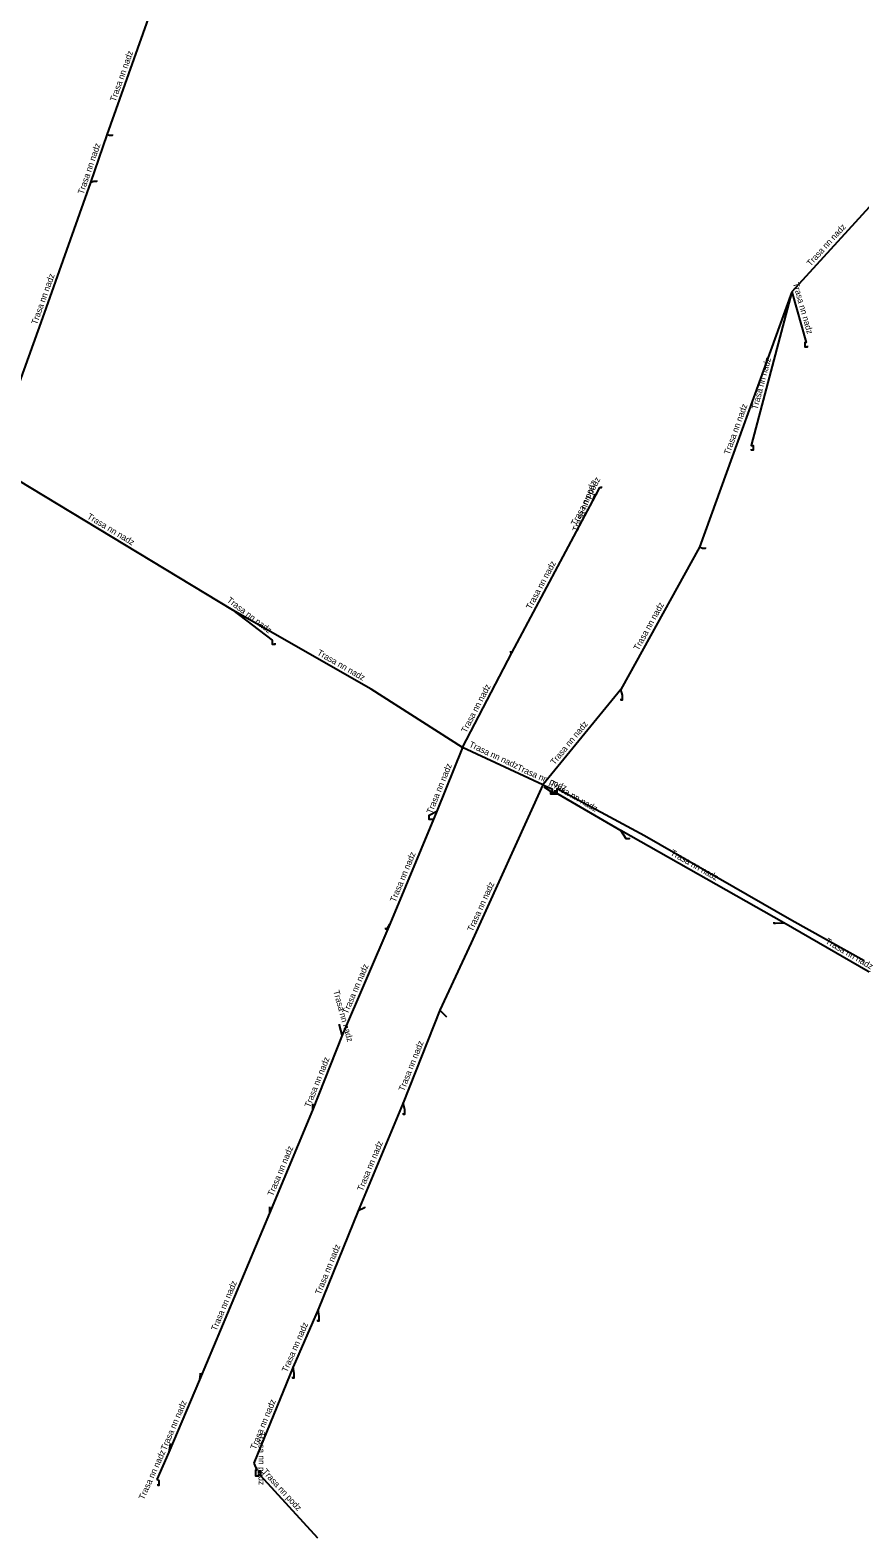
# Model space of a CAD drawing. Extents: x -742082 to -717476, y -1040737 to -1024597.
# Drawn here: x -736137.3 to -736004.4, y -1032673.2 to -1032431.7 of the extents above; entities that cross this region are included whole.
import ezdxf

# ---------------------------------------------------------------- set-up
doc = ezdxf.new("R2010")
doc.units = 0
for name, color, linetype in [('Level 13', 7, 'Continuous'), ('Level 14', 7, 'Continuous'), ('Level 15', 7, 'Continuous'), ('Level 20', 7, 'Continuous')]:
    doc.layers.add(name, color=color, linetype=linetype)

msp = doc.modelspace()

# ---------------------------------------------------------------- linework, layer by layer
at = {"layer": 'Level 13'}
for p, q in [((-736125, -1032448.5), (-736117.2, -1032426.5)), ((-736127.6, -1032456.1), (-736125, -1032448.5)), ((-736000.12, -1032456.95), (-736015.31, -1032473.63)), ((-736015.31, -1032473.63), (-736030.1, -1032514.5)), ((-736104.86, -1032524.63), (-736141.51, -1032502.48)), ((-736060.18, -1032531.44), (-736047.21, -1032507.11)), ((-736030.1, -1032514.5), (-736042.7, -1032537.3)), ((-736068.06, -1032546.59), (-736060.18, -1032531.44)), ((-736042.7, -1032537.3), (-736055.22, -1032552.57)), ((-736068.06, -1032546.59), (-736072.2, -1032556.8)), ((-736055.22, -1032552.57), (-736068.06, -1032546.59)), ((-736072.2, -1032556.8), (-736079.7, -1032574.9)), ((-736016.6, -1032574.7), (-736042.7, -1032559.9)), ((-736079.7, -1032574.9), (-736087.34, -1032592.71)), ((-735993.1, -1032588.3), (-736016.6, -1032574.7)), ((-736071.7, -1032588.7), (-736077.6, -1032603.5)), ((-736071.7, -1032588.7), (-736070.64, -1032589.76)), ((-736087.34, -1032592.71), (-736092.1, -1032604.7)), ((-736092.1, -1032604.7), (-736099, -1032621.2)), ((-736077.6, -1032603.5), (-736084.8, -1032620.8)), ((-736099, -1032621.2), (-736110.2, -1032647.9)), ((-736084.8, -1032620.8), (-736091.2, -1032636.6)), ((-736091.2, -1032636.6), (-736095.2, -1032645.8)), ((-736095.2, -1032645.8), (-736101.52, -1032661.25)), ((-736110.2, -1032647.9), (-736115.1, -1032659.5)), ((-736115.1, -1032659.5), (-736117.04, -1032663.83))]:
    msp.add_line(p, q, dxfattribs=at)
for points in [[(-736124.2, -1032448.4), (-736124.2, -1032448.56), (-736124.65, -1032448.56), (-736125, -1032448.5)], [(-736126.7, -1032455.8), (-736126.7, -1032455.96), (-736127.15, -1032455.96), (-736127.6, -1032456.1)], [(-736139.8, -1032490.3), (-736135.3, -1032477.8), (-736127.6, -1032456.1)], [(-736029.2, -1032514.6), (-736029.2, -1032514.76), (-736029.65, -1032514.76), (-736030.1, -1032514.5)], [(-736068.06, -1032546.59), (-736082.72, -1032537.28), (-736104.86, -1032524.63)], [(-736060.4, -1032531.2), (-736060.4, -1032531.36), (-736060.18, -1032531.44)], [(-736042.7, -1032538.8), (-736042.7, -1032538.96), (-736042.45, -1032538.96), (-736042.45, -1032538.25), (-736042.7, -1032537.3)], [(-736055.22, -1032552.57), (-736066.7, -1032577.91), (-736071.7, -1032588.7)], [(-736055.03, -1032552.9), (-736053.99, -1032553.61), (-736053.99, -1032554.05), (-736052.79, -1032554.05), (-736042.7, -1032559.9)], [(-736072.99, -1032558), (-736072.99, -1032558.16), (-736073.44, -1032558.16), (-736073.44, -1032557.45), (-736072.2, -1032556.8)], [(-736041.4, -1032561.1), (-736041.4, -1032561.26), (-736041.85, -1032561.26), (-736042.7, -1032559.9)], [(-736080.4, -1032575.5), (-736080.4, -1032575.66), (-736080.15, -1032575.66), (-736079.7, -1032574.9)], [(-736018.2, -1032574.6), (-736018.2, -1032574.76), (-736017.95, -1032574.76), (-736016.6, -1032574.7)], [(-736092.1, -1032603.7), (-736092.1, -1032603.86), (-736092.1, -1032604.7)], [(-736077.6, -1032605.2), (-736077.6, -1032605.36), (-736077.34, -1032605.36), (-736077.34, -1032604.65), (-736077.6, -1032603.5)], [(-736099, -1032620.2), (-736099, -1032620.36), (-736099, -1032621.2)], [(-736083.8, -1032620.2), (-736083.8, -1032620.36), (-736084.8, -1032620.8)], [(-736091.3, -1032638.3), (-736091.3, -1032638.46), (-736091.05, -1032638.46), (-736091.05, -1032637.75), (-736091.2, -1032636.6)], [(-736095.3, -1032647.4), (-736095.3, -1032647.56), (-736095.05, -1032647.56), (-736095.05, -1032646.85), (-736095.2, -1032645.8)], [(-736110.1, -1032646.8), (-736110.1, -1032646.96), (-736110.2, -1032647.9)], [(-736114.9, -1032658.1), (-736114.9, -1032658.26), (-736115.1, -1032659.5)], [(-736116.9, -1032664.6), (-736116.9, -1032664.76), (-736116.65, -1032664.76), (-736116.65, -1032664.05), (-736117.04, -1032663.83)]]:
    msp.add_lwpolyline(points, dxfattribs=at)
at = {"layer": 'Level 14'}
for points in [[(-736015.31, -1032473.63), (-736021.81, -1032498.25), (-736021.54, -1032498.25), (-736021.54, -1032498.96), (-736021.8, -1032498.96), (-736021.8, -1032498.8)], [(-736015.31, -1032473.63), (-736013, -1032481.75), (-736013.25, -1032481.75), (-736013.25, -1032482.46), (-736012.8, -1032482.46), (-736012.8, -1032482.3)], [(-736104.86, -1032524.63), (-736098.55, -1032529.43), (-736098.55, -1032530.06), (-736098.1, -1032530.06), (-736098.1, -1032529.9)], [(-736087.34, -1032592.71), (-736087.8, -1032591.06), (-736087.8, -1032590.9)]]:
    msp.add_lwpolyline(points, dxfattribs=at)
at = {"layer": 'Level 15'}
for points in [[(-736047.21, -1032507.11), (-736046.09, -1032504.96), (-736045.8, -1032504.96), (-736045.8, -1032504.8)], [(-736047.21, -1032507.11), (-736046.84, -1032506.08), (-736046.61, -1032506.08), (-736046.61, -1032505.92)], [(-736055.22, -1032552.57), (-736053.71, -1032553.23), (-736053.71, -1032553.74), (-736053.23, -1032553.74), (-736053.23, -1032553.47)], [(-736053.25, -1032553.47), (-736053.25, -1032553.84), (-736052.9, -1032553.84), (-736052.9, -1032553.17), (-736038.93, -1032560.7), (-736015.33, -1032574.27), (-736003.74, -1032580.74)], [(-736101.52, -1032661.25), (-736101.01, -1032662.35), (-736101.25, -1032662.35), (-736101.25, -1032663.26), (-736100.7, -1032663.26), (-736100.7, -1032663)], [(-736100.7, -1032662.89), (-736100.7, -1032662.45), (-736100.45, -1032662.45), (-736100.45, -1032663.16), (-736100.47, -1032663.16), (-736091.3, -1032673.2)]]:
    msp.add_lwpolyline(points, dxfattribs=at)

# ---------------------------------------------------------------- texts
at = {"layer": 'Level 20'}
for s, rotation, p in [('Trasa nn nadz', 70.4783, (-736123.67, -1032443.26)), ('Trasa nn nadz', 71.1139, (-736128.81, -1032458.09)), ('Trasa nn nadz', 47.6768, (-736012.32, -1032469.6)), ('Trasa nn nadz', 70.4633, (-736136.25, -1032478.97)), ('Trasa nn nadz', 285.883, (-736015.18, -1032472.26)), ('Trasa nn nadz', 75.2158, (-736020.82, -1032492.56)), ('Trasa nn nadz', 70.1059, (-736025.31, -1032499.81)), ('Trasa nn podz', 62.4396, (-736049.9, -1032511.18)), ('Trasa nn podz', 70.0399, (-736049.57, -1032512.15)), ('Trasa nn nadz', 328.8493, (-736128.31, -1032509.87)), ('Trasa nn nadz', 61.9385, (-736057.09, -1032524.59)), ('Trasa nn nadz', 322.7194, (-736105.91, -1032523.2)), ('Trasa nn nadz', 61.0736, (-736039.88, -1032531.16)), ('Trasa nn nadz', 330.2579, (-736091.46, -1032531.71)), ('Trasa nn nadz', 62.5196, (-736067.47, -1032544.36)), ('Trasa nn nadz', 50.6514, (-736053.33, -1032549.48)), ('Trasa nn nadz', 335.0271, (-736067.13, -1032546.47)), ('Trasa nn nadz', 67.9282, (-736072.96, -1032557.33)), ('Trasa nn podz', 336.4682, (-736059.45, -1032550.18)), ('Trasa nn nadz', 329.9087, (-736054.19, -1032552.66)), ('Trasa nn nadz', 67.4926, (-736078.82, -1032571.47)), ('Trasa nn nadz', 330.4446, (-736034.87, -1032563.76)), ('Trasa nn nadz', 65.6276, (-736066.46, -1032576.18)), ('Trasa nn nadz', 329.941, (-736010.04, -1032577.92)), ('Trasa nn nadz', 66.782, (-736086.46, -1032589.39)), ('Trasa nn nadz', 285.5688, (-736088.8, -1032585.62)), ('Trasa nn nadz', 68.2654, (-736077.44, -1032601.76)), ('Trasa nn nadz', 68.347, (-736092.5, -1032604.36)), ('Trasa nn nadz', 67.4037, (-736084.08, -1032617.76)), ('Trasa nn nadz', 67.3062, (-736098.44, -1032618.56)), ('Trasa nn nadz', 67.9489, (-736090.82, -1032634.34)), ('Trasa nn nadz', 67.2431, (-736107.49, -1032640.15)), ('Trasa nn nadz', 66.5014, (-736096.17, -1032646.77)), ('Trasa nn nadz', 67.1001, (-736115.56, -1032659.3)), ('Trasa nn nadz', 67.7524, (-736101.2, -1032659.16)), ('Trasa nn podz', 270, (-736100.75, -1032656.2)), ('Trasa nn nadz', 65.8659, (-736119.1, -1032667.2)), ('Trasa nn podz', 312.4105, (-736100.24, -1032662.67))]:
    msp.add_text(s, height=1, rotation=rotation, dxfattribs=at).set_placement(p)

doc.saveas('drawing.dxf')
